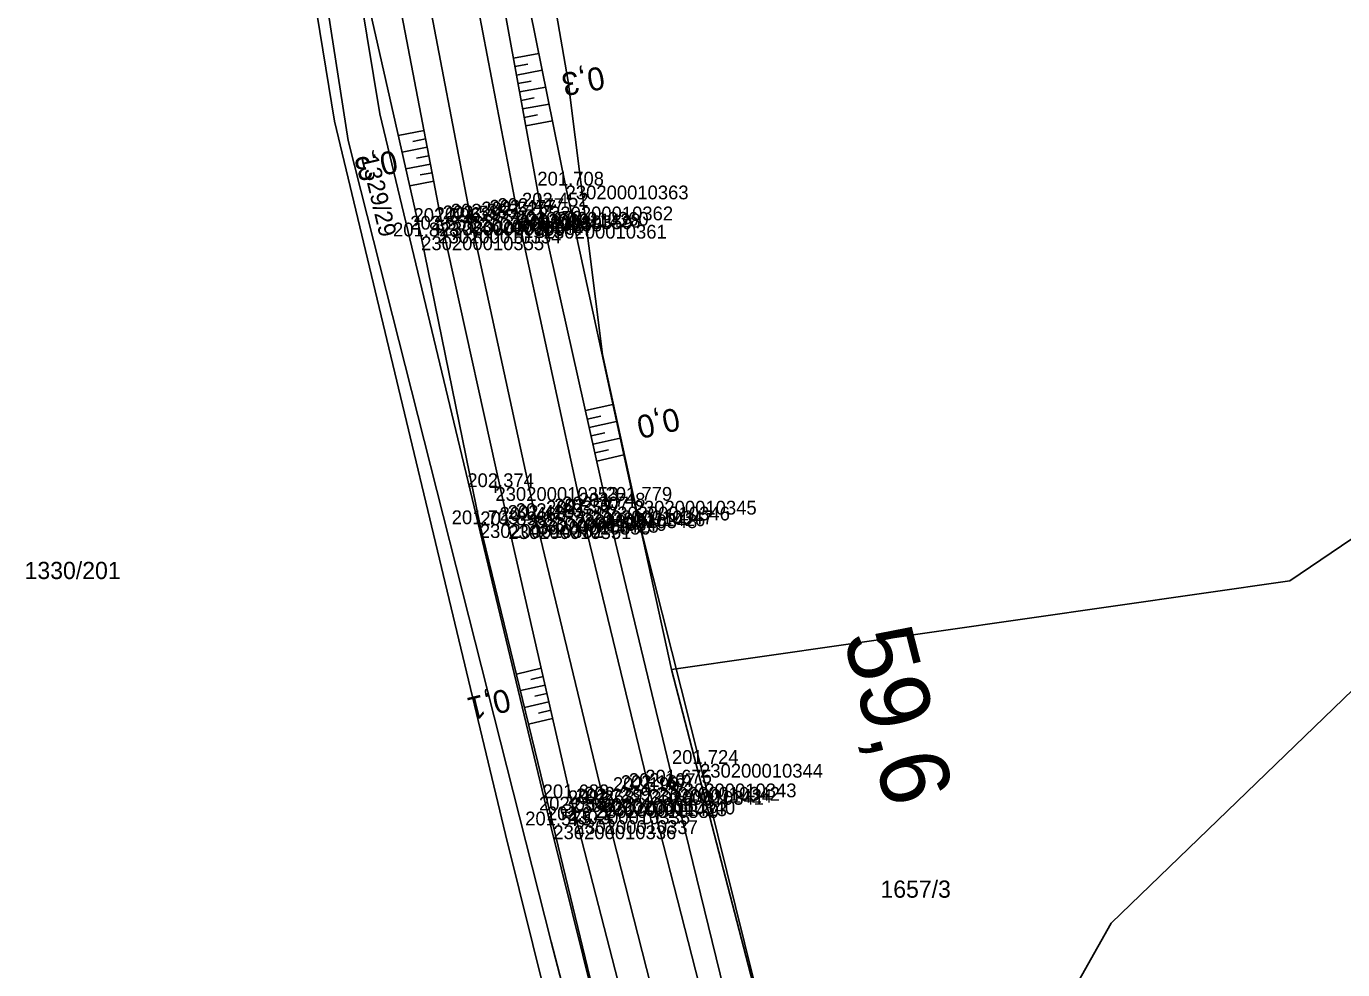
# Model space of a CAD drawing. Extents: x -563148 to -561712, y -1182311 to -1179502.
# Drawn here: x -562517.4 to -562402.8, y -1181774.7 to -1181692.5 of the extents above; entities that cross this region are included whole.
import ezdxf

# ---------------------------------------------------------------- set-up
doc = ezdxf.new("R2010")
doc.units = 0
for name, color, linetype in [('Vrstva 1', 7, 'Continuous'), ('Vrstva 4', 7, 'Continuous'), ('Vrstva 48', 7, 'Continuous'), ('Vrstva 49', 7, 'Continuous'), ('Vrstva 53', 7, 'Continuous'), ('Vrstva 55', 7, 'Continuous'), ('Vrstva 57', 7, 'Continuous'), ('Vrstva 60', 7, 'Continuous'), ('Vrstva 61', 7, 'Continuous'), ('Vrstva 7', 7, 'Continuous')]:
    doc.layers.add(name, color=color, linetype=linetype)

msp = doc.modelspace()

# ---------------------------------------------------------------- linework, layer by layer
at = {"layer": 'Vrstva 1'}
for points in [[(-562494.78, -1181561.72), (-562492, -1181588.79), (-562489.23, -1181614.7), (-562486.36, -1181638.51), (-562483.08, -1181661.63), (-562478.81, -1181687.1), (-562474.65, -1181708.83), (-562469.02, -1181734.85), (-562463.2, -1181758.95), (-562455.45, -1181789.24), (-562449.59, -1181811.86), (-562443.9, -1181833.9), (-562437.91, -1181857.15), (-562431.46, -1181882.16), (-562425.09, -1181906.77)], [(-562498.83, -1181562.33), (-562496.03, -1181589.56), (-562493.27, -1181615.3), (-562490.4, -1181639.1), (-562487.12, -1181662.18), (-562482.81, -1181687.92), (-562478.71, -1181709.32), (-562473.06, -1181735.42), (-562467.12, -1181760.11), (-562459.38, -1181790.41), (-562453.56, -1181813.02), (-562447.89, -1181834.96), (-562441.86, -1181858.29), (-562435.35, -1181883.46), (-562429.04, -1181907.88)]]:
    msp.add_lwpolyline(points, dxfattribs=at)
at = {"layer": 'Vrstva 4'}
for points in [[(-562492.69, -1181561.57), (-562489.58, -1181589.45), (-562487.07, -1181614.52), (-562483.98, -1181638.5), (-562480.82, -1181661.22), (-562476.64, -1181686.4), (-562472.37, -1181709.79), (-562466.87, -1181734.35), (-562461.07, -1181758.47), (-562453.65, -1181788.85), (-562447.14, -1181812.48), (-562441.76, -1181833.32), (-562435.97, -1181855.74), (-562429.08, -1181881.43), (-562423.04, -1181906.03)], [(-562356.6, -1182197.06), (-562363.67, -1182172.63), (-562369.11, -1182150.39), (-562376, -1182124.38), (-562381.96, -1182100.17), (-562388.24, -1182075.66), (-562394.26, -1182052.53), (-562401.09, -1182025.77), (-562406.12, -1182006.05), (-562411.7, -1181984.7), (-562419.19, -1181956.16), (-562425.49, -1181931.88), (-562431.35, -1181908.29), (-562438.22, -1181883.65), (-562444.12, -1181860.12), (-562450.4, -1181835.43), (-562455.98, -1181813.76), (-562461.84, -1181791.5), (-562470.01, -1181759.75), (-562475.45, -1181735.97), (-562481.27, -1181709.55), (-562485.29, -1181688.62), (-562489.63, -1181662.78), (-562492.85, -1181639.28)]]:
    msp.add_lwpolyline(points, dxfattribs=at)
at = {"layer": 'Vrstva 48'}
for p, q in [((-562475.02, -1181695.27), (-562472.8, -1181694.87)), ((-562474.89, -1181696.01), (-562473.77, -1181695.8)), ((-562474.75, -1181696.75), (-562472.5, -1181696.34)), ((-562474.62, -1181697.48), (-562473.48, -1181697.28)), ((-562474.48, -1181698.22), (-562472.2, -1181697.81)), ((-562474.35, -1181698.96), (-562473.2, -1181698.75)), ((-562474.21, -1181699.7), (-562471.91, -1181699.28)), ((-562474.08, -1181700.44), (-562472.92, -1181700.23)), ((-562473.94, -1181701.17), (-562471.61, -1181700.75)), ((-562482.8, -1181701.57), (-562485.04, -1181702.01)), ((-562482.52, -1181703.05), (-562484.71, -1181703.47)), ((-562482.66, -1181702.31), (-562483.77, -1181702.53)), ((-562482.38, -1181703.78), (-562483.46, -1181703.99)), ((-562482.23, -1181704.52), (-562484.38, -1181704.93)), ((-562482.09, -1181705.26), (-562483.15, -1181705.46)), ((-562481.95, -1181705.99), (-562484.05, -1181706.4)), ((-562468.74, -1181725.99), (-562466.35, -1181725.46)), ((-562468.58, -1181726.72), (-562467.39, -1181726.46)), ((-562468.41, -1181727.45), (-562466.04, -1181726.92)), ((-562468.25, -1181728.19), (-562467.06, -1181727.92)), ((-562468.08, -1181728.92), (-562465.72, -1181728.39)), ((-562467.92, -1181729.65), (-562466.74, -1181729.39)), ((-562467.76, -1181730.38), (-562465.4, -1181729.85)), ((-562472.6, -1181748.43), (-562474.76, -1181748.93)), ((-562472.26, -1181749.9), (-562474.4, -1181750.38)), ((-562472.43, -1181749.16), (-562473.51, -1181749.41)), ((-562471.93, -1181751.36), (-562474.04, -1181751.84)), ((-562472.1, -1181750.63), (-562473.16, -1181750.87)), ((-562471.76, -1181752.09), (-562472.82, -1181752.33)), ((-562471.6, -1181752.82), (-562473.69, -1181753.3))]:
    msp.add_line(p, q, dxfattribs=at)
at = {"layer": 'Vrstva 49'}
for points in [[(-562492.69, -1181561.57), (-562489.58, -1181589.45), (-562487.07, -1181614.52), (-562483.98, -1181638.5), (-562480.82, -1181661.22), (-562476.64, -1181686.4), (-562472.37, -1181709.79), (-562466.87, -1181734.35), (-562461.07, -1181758.47), (-562453.65, -1181788.85), (-562447.14, -1181812.48), (-562441.76, -1181833.32), (-562435.97, -1181855.74), (-562429.08, -1181881.43), (-562423.04, -1181906.03)], [(-562419.93, -1181905), (-562426.04, -1181880.28), (-562431.85, -1181855.4), (-562438.18, -1181832.68), (-562444.2, -1181811.82), (-562451.04, -1181787.93), (-562458.76, -1181756.76), (-562464.54, -1181733.84), (-562470.47, -1181706.38), (-562474.63, -1181685.81), (-562478.42, -1181661.19), (-562481.77, -1181640.57), (-562484.68, -1181614.02), (-562487.28, -1181589.39), (-562490.19, -1181561.46)], [(-562494.74, -1181639.25), (-562491.93, -1181663.18), (-562488.02, -1181688.86), (-562483.05, -1181710.81), (-562477.94, -1181735.88), (-562471.54, -1181762.12), (-562464.06, -1181793.11), (-562458.19, -1181815.37), (-562452.51, -1181835.57), (-562445.7, -1181861.04), (-562439.74, -1181884.96), (-562433.65, -1181909.28)], [(-562356.6, -1182197.06), (-562363.67, -1182172.63), (-562369.11, -1182150.39), (-562376, -1182124.38), (-562381.96, -1182100.17), (-562388.24, -1182075.66), (-562394.26, -1182052.53), (-562401.09, -1182025.77), (-562406.12, -1182006.05), (-562411.7, -1181984.7), (-562419.19, -1181956.16), (-562425.49, -1181931.88), (-562431.35, -1181908.29), (-562438.22, -1181883.65), (-562444.12, -1181860.12), (-562450.4, -1181835.43), (-562455.98, -1181813.76), (-562461.84, -1181791.5), (-562470.01, -1181759.75), (-562475.45, -1181735.97), (-562481.27, -1181709.55), (-562485.29, -1181688.62), (-562489.63, -1181662.78), (-562492.85, -1181639.28)]]:
    msp.add_lwpolyline(points, dxfattribs=at)
at = {"layer": 'Vrstva 53'}
for p, q in [((-562486.65, -1181700.13), (-562496.65, -1181639.14)), ((-562475.61, -1181666.51), (-562470.24, -1181697.31)), ((-562470.24, -1181697.31), (-562467.27, -1181721.1)), ((-562471.81, -1181761.96), (-562486.65, -1181700.13)), ((-562467.27, -1181721.1), (-562461.24, -1181748.55)), ((-562461.24, -1181748.55), (-562443.55, -1181816.74)), ((-562451.04, -1181845.92), (-562471.81, -1181761.96))]:
    msp.add_line(p, q, dxfattribs=at)
at = {"layer": 'Vrstva 55'}
for p, q in [((-562500.18, -1181642.33), (-562490.6, -1181700.78)), ((-562498.9, -1181641.83), (-562489.4, -1181702.45)), ((-562475.69, -1181762.92), (-562490.6, -1181700.78)), ((-562489.4, -1181702.45), (-562471.73, -1181772.25)), ((-562407.4, -1181740.8), (-562397.96, -1181734.41)), ((-562461.24, -1181748.55), (-562407.4, -1181740.8)), ((-562398.82, -1181747.32), (-562422.96, -1181770.64)), ((-562454.92, -1181846.88), (-562475.69, -1181762.92)), ((-562422.96, -1181770.64), (-562432.65, -1181787.76)), ((-562471.73, -1181772.25), (-562452.23, -1181846.48))]:
    msp.add_line(p, q, dxfattribs=at)
at = {"layer": 'Vrstva 60'}
for p, q in [((-562470.47, -1181706.38), (-562470.47, -1181706.38)), ((-562475.36, -1181708.98), (-562475.36, -1181708.98)), ((-562474.65, -1181708.83), (-562474.65, -1181708.83)), ((-562473.95, -1181708.68), (-562473.95, -1181708.68)), ((-562471.82, -1181708.21), (-562471.82, -1181708.21)), ((-562481.27, -1181709.55), (-562481.27, -1181709.55)), ((-562479.42, -1181709.47), (-562479.42, -1181709.47)), ((-562478.71, -1181709.32), (-562478.71, -1181709.32)), ((-562478.01, -1181709.17), (-562478.01, -1181709.17)), ((-562472.37, -1181709.79), (-562472.37, -1181709.79)), ((-562483.05, -1181710.81), (-562483.05, -1181710.81)), ((-562481.55, -1181710.22), (-562481.55, -1181710.22)), ((-562476.58, -1181732.65), (-562476.58, -1181732.65)), ((-562464.54, -1181733.84), (-562464.54, -1181733.84)), ((-562472.36, -1181735.26), (-562472.36, -1181735.26)), ((-562469.71, -1181735.02), (-562469.71, -1181735.02)), ((-562469.02, -1181734.85), (-562469.02, -1181734.85)), ((-562468.32, -1181734.68), (-562468.32, -1181734.68)), ((-562466.87, -1181734.35), (-562466.87, -1181734.35)), ((-562477.94, -1181735.88), (-562477.94, -1181735.88)), ((-562475.45, -1181735.97), (-562475.45, -1181735.97)), ((-562473.77, -1181735.58), (-562473.77, -1181735.58)), ((-562473.06, -1181735.42), (-562473.06, -1181735.42)), ((-562458.76, -1181756.76), (-562458.76, -1181756.76)), ((-562463.9, -1181759.12), (-562463.9, -1181759.12)), ((-562463.2, -1181758.95), (-562463.2, -1181758.95)), ((-562462.51, -1181758.77), (-562462.51, -1181758.77)), ((-562461.07, -1181758.47), (-562461.07, -1181758.47)), ((-562470.01, -1181759.75), (-562470.01, -1181759.75)), ((-562467.82, -1181760.27), (-562467.82, -1181760.27)), ((-562467.12, -1181760.11), (-562467.12, -1181760.11)), ((-562466.41, -1181759.96), (-562466.41, -1181759.96)), ((-562470.34, -1181760.82), (-562470.34, -1181760.82)), ((-562469.66, -1181761.67), (-562469.66, -1181761.67)), ((-562471.54, -1181762.12), (-562471.54, -1181762.12))]:
    msp.add_line(p, q, dxfattribs=at)
at = {"layer": 'Vrstva 7'}
for p, q in [((-562471.82, -1181707.71), (-562471.82, -1181708.71)), ((-562472.32, -1181708.21), (-562471.32, -1181708.21)), ((-562481.55, -1181709.72), (-562481.55, -1181710.72)), ((-562482.05, -1181710.22), (-562481.05, -1181710.22)), ((-562477.08, -1181732.65), (-562476.08, -1181732.65)), ((-562476.58, -1181732.15), (-562476.58, -1181733.15)), ((-562470.35, -1181760.78), (-562470.32, -1181760.87)), ((-562470.16, -1181761.67), (-562469.16, -1181761.67)), ((-562469.66, -1181761.17), (-562469.66, -1181762.17))]:
    msp.add_line(p, q, dxfattribs=at)
for centre, radius in [((-562467.13, -1181760.05), 0.75), ((-562470.34, -1181760.82), 0.5)]:
    msp.add_circle(centre, radius, dxfattribs=at)

# ---------------------------------------------------------------- texts
at = {"layer": 'Vrstva 48'}
for s, rotation, p in [('0,3', 190.3249, (-562467.28, -1181695.97)), ('0,3', 192.7464, (-562485.37, -1181703.26)), ('0,0', 192.6382, (-562460.79, -1181725.7)), ('0,1', 193.7065, (-562475.56, -1181750.17))]:
    msp.add_text(s, height=2, rotation=rotation, dxfattribs=at).set_placement(p)
at = {"layer": 'Vrstva 57'}
msp.add_text('1329/29', height=1.5, rotation=283.2882, dxfattribs=at).set_placement((-562488.3, -1181703.91))
for s, p in [('1330/201', (-562517.59, -1181740.66)), ('1657/3', (-562443.05, -1181768.42))]:
    msp.add_text(s, height=1.5, dxfattribs=at).set_placement(p)
at = {"layer": 'Vrstva 60'}
for s, p in [('230200010363', (-562470.47, -1181707.58)), ('230200010359', (-562475.36, -1181710.18)), ('230200011428', (-562474.65, -1181710.03)), ('230200010360', (-562473.95, -1181709.88)), ('230200010362', (-562471.82, -1181709.41)), ('230200010356', (-562481.27, -1181710.75)), ('230200010357', (-562479.42, -1181710.67)), ('230200011427', (-562478.71, -1181710.52)), ('230200010358', (-562478.01, -1181710.37)), ('230200010361', (-562472.37, -1181711)), ('230200010355', (-562483.05, -1181712.01)), ('230200010354', (-562481.55, -1181711.42)), ('230200010353', (-562476.58, -1181733.85)), ('230200010345', (-562464.54, -1181735.04)), ('230200010349', (-562472.36, -1181736.46)), ('230200010348', (-562469.71, -1181736.22)), ('230200011426', (-562469.02, -1181736.05)), ('230200010347', (-562468.32, -1181735.88)), ('230200010346', (-562466.87, -1181735.55)), ('230200010352', (-562477.94, -1181737.08)), ('230200010351', (-562475.45, -1181737.17)), ('230200010350', (-562473.77, -1181736.78)), ('230200011425', (-562473.06, -1181736.62)), ('230200010344', (-562458.76, -1181757.96)), ('230200010341', (-562463.9, -1181760.32)), ('230200011424', (-562463.2, -1181760.15)), ('230200010342', (-562462.51, -1181759.97)), ('230200010343', (-562461.07, -1181759.67)), ('230200010338', (-562470.01, -1181760.95)), ('230200010339', (-562467.82, -1181761.47)), ('230200011423', (-562467.12, -1181761.31)), ('230200010340', (-562466.41, -1181761.16)), ('230200010335', (-562470.34, -1181762.02)), ('230200010337', (-562469.66, -1181762.87)), ('230200010336', (-562471.54, -1181763.32))]:
    msp.add_text(s, height=1.2, dxfattribs=at).set_placement(p)
at = {"layer": 'Vrstva 61'}
for s, p in [('201.708', (-562472.93, -1181706.38)), ('202.525', (-562477.81, -1181708.98)), ('202.477', (-562477.1, -1181708.83)), ('202.477', (-562476.4, -1181708.68)), ('202.452', (-562474.27, -1181708.21)), ('202.558', (-562484, -1181710.22)), ('202.096', (-562483.72, -1181709.55)), ('202.629', (-562481.87, -1181709.47)), ('202.585', (-562481.17, -1181709.32)), ('202.585', (-562480.47, -1181709.17)), ('201.970', (-562474.82, -1181709.79)), ('201.823', (-562485.5, -1181710.81)), ('202.374', (-562479.03, -1181732.65)), ('201.779', (-562466.99, -1181733.84)), ('202.420', (-562475.51, -1181735.42)), ('202.420', (-562474.81, -1181735.26)), ('202.357', (-562472.17, -1181735.02)), ('202.307', (-562471.47, -1181734.85)), ('202.307', (-562470.77, -1181734.68)), ('201.748', (-562469.32, -1181734.35)), ('201.703', (-562480.39, -1181735.88)), ('201.896', (-562477.9, -1181735.97)), ('202.468', (-562476.22, -1181735.58)), ('201.724', (-562461.21, -1181756.76)), ('202.193', (-562466.35, -1181759.12)), ('202.167', (-562465.66, -1181758.95)), ('202.167', (-562464.96, -1181758.77)), ('201.675', (-562463.53, -1181758.47)), ('201.689', (-562472.47, -1181759.75)), ('202.268', (-562470.27, -1181760.27)), ('202.239', (-562469.57, -1181760.11)), ('202.239', (-562468.87, -1181759.96)), ('202.054', (-562472.79, -1181760.82)), ('202.222', (-562472.1, -1181761.67)), ('201.575', (-562473.99, -1181762.12))]:
    msp.add_text(s, height=1.2, dxfattribs=at).set_placement(p)
at = {"layer": 'Vrstva 7'}
msp.add_text('59,6', height=6, rotation=284.3158, dxfattribs=at).set_placement((-562446.3, -1181745.66))

doc.saveas('drawing.dxf')
